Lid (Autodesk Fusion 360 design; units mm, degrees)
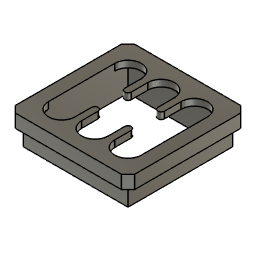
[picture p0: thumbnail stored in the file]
sketch "Sketch1" plane through (0, 0, 16.5) normal (0, 0, -1) x axis (1, 0, 0)
  line L1 (3, -2) -> (3, -5)
  line L2 (2, -2) -> (3, -2)
  line L3 (2, -5) -> (2, -2)
  line L4 (-2, -2) -> (-2, -5)
  line L5 (-3, -2) -> (-2, -2)
  line L6 (-3, -5) -> (-3, -2)
  line L7 (-7, 5) -> (-7, -5)
  line L8 (-3, 2) -> (-3, 5)
  line L9 (-2, 2) -> (-3, 2)
  line L10 (-2, 5) -> (-2, 2)
  line L11 (2, 2) -> (2, 5)
  line L12 (3, 2) -> (2, 2)
  line L13 (3, 5) -> (3, 2)
  line L14 (7, -5) -> (7, 5)
  line L15 (-8, 9) -> (8, 9)
  line L16 (-9, 8) -> (-8, 9)
  line L17 (-9, -8) -> (-9, 8)
  line L18 (-8, -9) -> (-9, -8)
  line L19 (8, -9) -> (-8, -9)
  line L20 (9, -8) -> (8, -9)
  line L21 (9, 8) -> (9, -8)
  line L22 (8, 9) -> (9, 8)
  line L23 (-3, 7) -> (-3, 2.5)
  line L24 (-7, 7) -> (-3, 7)
  line L25 (-7, -7) -> (-7, 7)
  line L26 (-3, -7) -> (-7, -7)
  line L27 (-3, -2.5) -> (-3, -7)
  line L28 (-2, -7) -> (-2, -2.5)
  line L29 (2, -7) -> (-2, -7)
  line L30 (2, -2.5) -> (2, -7)
  line L31 (3, -7) -> (3, -2.5)
  line L32 (7, -7) -> (3, -7)
  line L33 (7, 7) -> (7, -7)
  line L34 (3, 7) -> (7, 7)
  line L35 (3, 2.5) -> (3, 7)
  line L36 (2, 7) -> (2, 2.5)
  line L37 (-2, 7) -> (2, 7)
  line L38 (-2, 2.5) -> (-2, 7)
  line L39 (-3, 7) -> (-3, 2.5)
  line L40 (2, 7) -> (3, 7)
  line L41 (-3, 7) -> (-2, 7)
  line L42 (-2, -7) -> (-3, -7)
  line L43 (-2, -2.5) -> (-3, -2.5)
  line L44 (3, -7) -> (2, -7)
  line L45 (3, -2.5) -> (2, -2.5)
  line L46 (2, -2) -> (2, -2.5)
  line L47 (3, -2.5) -> (3, -2)
  line L48 (2, -2) -> (3, -2)
  line L49 (-2, -2) -> (-2, -2.5)
  line L50 (-3, -2) -> (-2, -2)
  line L51 (-3, -2.5) -> (-3, -2)
  line L52 (-3, 2) -> (-3, 2.5)
  line L53 (-2, 2) -> (-3, 2)
  line L54 (-2, 2) -> (-2, 2.5)
  line L55 (2, 2) -> (2, 2.5)
  line L56 (2, 2) -> (3, 2)
  line L57 (3, 2.5) -> (3, 2)
  line L58 (-2, 2.5) -> (-3, 2.5)
  line L59 (3, 2.5) -> (2, 2.5)
  arc A1 centre (0, -5) radius 2 clockwise from (2, -5) to (-2, -5)
  arc A2 centre (-5, -5) radius 2 clockwise from (-3, -5) to (-7, -5)
  arc A3 centre (-5, 5) radius 2 clockwise from (-7, 5) to (-3, 5)
  arc A4 centre (0, 5) radius 2 clockwise from (-2, 5) to (2, 5)
  arc A5 centre (5, 5) radius 2 clockwise from (3, 5) to (7, 5)
  arc A6 centre (5, -5) radius 2 clockwise from (7, -5) to (3, -5)
  arc A7 centre (-2.5, -2.5) radius 0.5 clockwise from (-3, -2.5) to (-2, -2.5)
  arc A8 centre (2.5, -2.5) radius 0.5 clockwise from (2, -2.5) to (3, -2.5)
  arc A9 centre (2.5, 2.5) radius 0.5 clockwise from (3, 2.5) to (2, 2.5)
  arc A10 centre (-2.5, 2.5) radius 0.5 clockwise from (-2, 2.5) to (-3, 2.5)
  point P38 (-3, -2.5)
  point P37 (-2, -2.5)
  point P41 (2, -2.5)
  point P40 (3, -2.5)
  point P43 (2, 2.5)
  point P44 (3, 2.5)
  point P46 (-3, 2.5)
  point P47 (-2, 2.5)
  point P4 (2, -2)
  point P60 (2, -2)
  point P3 (3, -2)
  point P61 (3, -2)
  point P62 (3, -2)
  point P63 (2, -2)
  point P8 (-2, -2)
  point P64 (-2, -2)
  point P9 (-3, -2)
  point P65 (-3, -2)
  point P16 (-3, 2)
  point P66 (-3, 2)
  point P17 (-2, 2)
  point P67 (-2, 2)
  point P21 (2, 2)
  point P68 (2, 2)
  point P22 (3, 2)
  point P69 (3, 2)
  coincident L6 P38
  coincident L4 P37
  coincident L3 P41
  coincident L1 P40
  coincident L11 P43
  coincident L13 P44
  coincident L8 P46
  coincident L10 P47
  tangent A10 L23
  parallel L8 L23
  perpendicular L8 L24
  perpendicular L24 L25
  perpendicular L7 L26
  tangent A7 L27
  tangent A7 L28
  parallel L4 L28
  perpendicular L28 L29
  tangent A8 L30
  tangent A8 L31
  parallel L1 L31
  perpendicular L31 L32
  perpendicular L32 L33
  perpendicular L14 L34
  tangent A9 L35
  tangent A9 L36
  parallel L11 L36
  perpendicular L23 L37
  tangent A10 L38
  perpendicular L36 L40
  perpendicular L23 L41
  perpendicular L28 L42
  perpendicular L28 L43
  perpendicular L31 L44
  perpendicular L1 L45
  coincident P4 P60
  coincident P3 P61
  coincident P3 P62
  coincident P4 P63
  coincident P8 P64
  coincident P9 P65
  coincident P16 P66
  tangent A10 L52
  coincident P17 P67
  tangent A10 L54
  coincident P21 P68
  coincident P22 P69
  tangent A9 L57
sketch "Sketch2" plane through (0, 0, 16.5) normal (0, 0, 1) x axis (-1, 0, 0)
  line L1 (7, -7) -> (7, 7)
  line L2 (-7, -7) -> (7, -7)
  line L3 (-7, 7) -> (-7, -7)
  line L4 (7, 7) -> (-7, 7)
  line L5 (-9, 8) -> (-8, 9)
  line L6 (-9, -8) -> (-9, 8)
  line L7 (-8, -9) -> (-9, -8)
  line L8 (8, -9) -> (-8, -9)
  line L9 (9, -8) -> (8, -9)
  line L10 (9, 8) -> (9, -8)
  line L11 (8, 9) -> (9, 8)
  line L12 (-8, 9) -> (8, 9)
  line L13 (-7, -7) -> (7, -7)
  line L14 (-7, 7) -> (-7, -7)
  line L15 (7, 7) -> (-7, 7)
  line L16 (7, -7) -> (7, 7)
  line L17 (9, -8) -> (8, -9)
  line L18 (9, 8) -> (9, -8)
  line L19 (9, 8) -> (8, 9)
  line L20 (-8, 9) -> (8, 9)
  line L21 (-9, 8) -> (-8, 9)
  line L22 (-9, -8) -> (-9, 8)
  line L23 (-8, -9) -> (-9, -8)
  line L24 (8, -9) -> (-8, -9)
  line L25 (7, 5) -> (7, -5)
  line L26 (3, -5) -> (3, 5)
  line L27 (5, 5) -> (5, -5)
  line L28 (-3, 5) -> (-3, -5)
  line L29 (-7, -5) -> (-7, 5)
  line L30 (-5, 5) -> (-5, -5)
  line L31 (2, 5) -> (2, -5)
  line L32 (-2, -5) -> (-2, 5)
  line L33 (0, 5) -> (0, -5)
  line L34 (-5, 2) -> (5, 2)
  line L35 (5, -2) -> (-5, -2)
  line L36 (-5, 0) -> (5, 0)
  line L37 (-7.9, -7.9) -> (7.9, -7.9)
  line L38 (-7.9, 7.9) -> (-7.9, -7.9)
  line L39 (7.9, 7.9) -> (-7.9, 7.9)
  line L40 (7.9, -7.9) -> (7.9, 7.9)
  arc A1 centre (5, 5) radius 2 clockwise from (3, 5) to (7, 5)
  arc A2 centre (5, -5) radius 2 clockwise from (7, -5) to (3, -5)
  arc A3 centre (-5, 5) radius 2 clockwise from (-7, 5) to (-3, 5)
  arc A4 centre (-5, -5) radius 2 clockwise from (-3, -5) to (-7, -5)
  arc A5 centre (0, 5) radius 2 clockwise from (-2, 5) to (2, 5)
  arc A6 centre (0, -5) radius 2 clockwise from (2, -5) to (-2, -5)
  arc A7 centre (-5, 0) radius 2 clockwise from (-5, -2) to (-5, 2)
  arc A8 centre (5, 0) radius 2 clockwise from (5, 2) to (5, -2)
  point P5 (-7, 7)
  point P16 (-7, 7)
  point P3 (7, -7)
  point P14 (7, -7)
  point P10 (8, -9)
  point P18 (8, -9)
  point P11 (9, -8)
  point P19 (9, -8)
  point P12 (9, 8)
  point P20 (9, 8)
  point P13 (8, 9)
  point P21 (8, 9)
  point P6 (-8, 9)
  point P22 (-8, 9)
  point P7 (-9, 8)
  point P23 (-9, 8)
  point P8 (-9, -8)
  point P24 (-9, -8)
  point P25 (-9, -8)
  point P9 (-8, -9)
  point P26 (-8, -9)
  point P50 (-5, 0)
  point P1 (0, 0)
  point P51 (0, 0)
  horizontal L13
  vertical L14
  horizontal L15
  vertical L16
  coincident P5 P16
  coincident P3 P14
  coincident P10 P18
  coincident P11 P19
  coincident P12 P20
  coincident P13 P21
  coincident P6 P22
  coincident P7 P23
  coincident P8 P24
  coincident P8 P25
  coincident P9 P26
  tangent L25 A1
  tangent A1 L26
  parallel L25 L26
  tangent L26 A2
  tangent L25 A2
  perpendicular L13 L27
  tangent L28 A3
  tangent A3 L29
  parallel L28 L29
  tangent L29 A4
  tangent L28 A4
  perpendicular L13 L30
  tangent L31 A5
  tangent A5 L32
  parallel L31 L32
  tangent L32 A6
  tangent L31 A6
  parallel L28 L33
  tangent L34 A7
  tangent A7 L35
  parallel L34 L35
  tangent L35 A8
  tangent L34 A8
  midpoint L30 P50
  perpendicular L30 L36
  coincident P1 P51
  midpoint L36 P51
  horizontal L37
  vertical L38
  horizontal L39
  vertical L40
  dimension "d1" distance L15 L39 = 0.9
  dimension "d2" distance L29 L38 = 0.9
  dimension "d3" distance L16 L40 = 0.9
  dimension "d4" distance L13 L37 = 0.9
extrude "Extrude1" new body sketch "Sketch2" profile of L1 L2 L3 L4 L5 L6 L7 L8 L9 L10 L11 L12 L13 L14 L15 L16 L17 L18 L19 L20 L21 L22 L23 L24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 along normal blind 2
extrude "Extrude2" cut sketch "Sketch1" profile of L1 L2 L3 L4 L5 L6 L8 L9 L10 L11 L12 L13 A7 A8 A9 A10 L46 L47 L48 L49 L50 L51 L52 L53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 against normal blind 4
extrude "Extrude3" cut sketch "Sketch1" profile of L1 L3 A1 L4 L6 A2 A3 L8 L10 A4 L11 L13 A5 A6 A7 A8 A9 A10 L23 L24 L25 L26 L27 L28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 against normal blind 1
extrude "Extrude4" add sketch "Sketch2" profile of L1 L2 L3 L4 L13 L14 L15 L16 L25 L29 L37 L38 L39 L40 against normal blind 2.9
